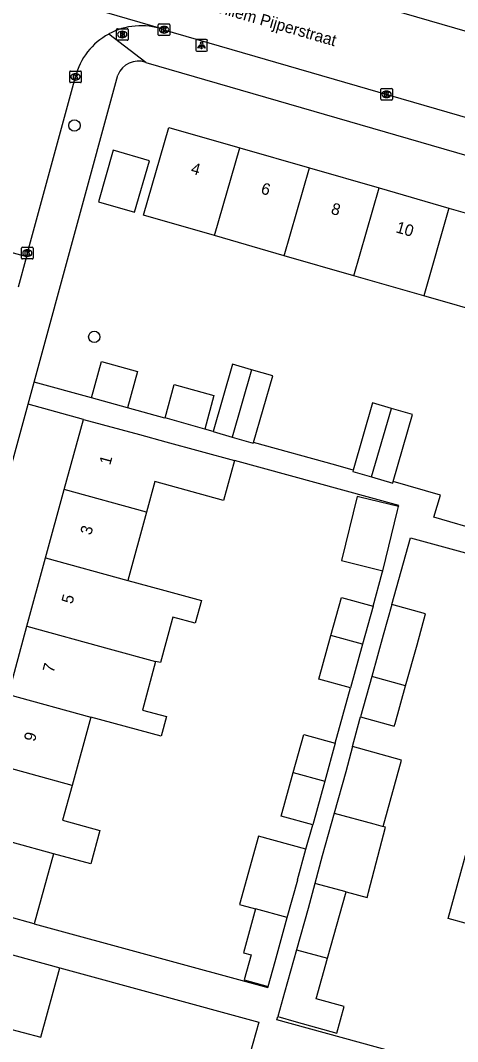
# Model space of a CAD drawing. Extents: x 159822 to 160765, y 380693 to 381634.
# Drawn here: x 160334.7 to 160372.4, y 381088.7 to 381176.6 of the extents above; entities that cross this region are included whole.
import ezdxf

# ---------------------------------------------------------------- set-up
doc = ezdxf.new("R2010")
doc.units = 0
for name, color, linetype in [('IMGEO_Boom', 7, 'Continuous'), ('IMGEO_Brandkraan', 7, 'Continuous'), ('IMGEO_Kolk', 7, 'Continuous'), ('IMGEO_Lichtpunt', 7, 'Continuous'), ('IMGEO_Openbare_ruimte_label', 7, 'Continuous'), ('IMGEO_Pand', 7, 'Continuous'), ('IMGEO_Pand_nummerreeks', 7, 'Continuous'), ('IMGEO_Rijbaan_lokaal_open', 7, 'Continuous'), ('IMGEO_Voetpad_open', 7, 'Continuous')]:
    doc.layers.add(name, color=color, linetype=linetype)

msp = doc.modelspace()

# ---------------------------------------------------------------- linework, layer by layer
at = {"layer": 'IMGEO_Boom'}
for centre in [(160339.349, 381167.541), (160341.058, 381149.34)]:
    msp.add_circle(centre, 0.489, dxfattribs=at)
at = {"layer": 'IMGEO_Brandkraan'}
for p, q in [((160342.97, 381174.95), (160342.97, 381175.802)), ((160343.045, 381175.876), (160343.897, 381175.876)), ((160343.458, 381175.656), (160343.483, 381175.656)), ((160343.971, 381175.802), (160343.971, 381174.95)), ((160343.897, 381174.876), (160343.045, 381174.876)), ((160343.481, 381175.096), (160343.456, 381175.096))]:
    msp.add_line(p, q, dxfattribs=at)
for points in [[(160342.97, 381174.95), (160342.97, 381175.802)], [(160343.045, 381175.876), (160343.897, 381175.876)], [(160343.318, 381175.576), (160343.318, 381175.176), (160343.531, 381175.176)], [(160343.549, 381175.576), (160343.318, 381175.576)], [(160343.497, 381175.495), (160343.443, 381175.495), (160343.443, 381175.419)], [(160343.443, 381175.419), (160343.496, 381175.419)], [(160343.971, 381175.802), (160343.971, 381174.95)], [(160343.897, 381174.876), (160343.045, 381174.876)], [(160343.505, 381175.343), (160343.443, 381175.343), (160343.443, 381175.262)], [(160343.443, 381175.262), (160343.505, 381175.262)]]:
    msp.add_lwpolyline(points, dxfattribs=at)
for centre, radius, start, end in [((160343.047, 381175.8), 0.0765, 91.55205, 178.44795), ((160343.047, 381175.8), 0.0765, 91.55205, 178.44795), ((160343.498, 381175.457), 0.0379, 267.82845, 90.93552), ((160343.553, 381175.431), 0.145, 59.4692, 91.53667), ((160343.578, 381175.478), 0.0922, 285.51372, 58.15012), ((160343.583, 381175.286), 0.105, 301.31148, 78.98903), ((160343.895, 381175.8), 0.0765, 1.55205, 88.44795), ((160343.895, 381175.8), 0.0765, 1.55205, 88.44795), ((160343.047, 381174.952), 0.0765, 181.55205, 268.44795), ((160343.047, 381174.952), 0.0765, 181.55205, 268.44795), ((160343.506, 381175.302), 0.0404, 269.87594, 90.50774), ((160343.537, 381175.427), 0.251, 268.66757, 293.53466), ((160343.895, 381174.952), 0.0765, 271.55205, 358.44795), ((160343.895, 381174.952), 0.0765, 271.55205, 358.44795)]:
    msp.add_arc(centre, radius, start, end, dxfattribs=at)
for centre, major_axis, ratio, start_param, end_param in [((160343.457, 381175.376), (-0.387, 0.002), 0.722429, 4.712389, 7.853982), ((160343.482, 381175.376), (-0.39, 0.002), 0.717154, 1.570796, 4.712389)]:
    msp.add_ellipse(centre, major_axis=major_axis, ratio=ratio, start_param=start_param, end_param=end_param, dxfattribs=at)
at = {"layer": 'IMGEO_Kolk'}
for p, q in [((160346.646, 381176.283), (160347.498, 381176.283)), ((160346.571, 381175.357), (160346.571, 381176.209)), ((160347.082, 381175.503), (160347.057, 381175.503)), ((160347.059, 381176.063), (160347.084, 381176.063)), ((160347.572, 381176.209), (160347.572, 381175.357)), ((160347.498, 381175.283), (160346.646, 381175.283)), ((160338.939, 381171.305), (160338.939, 381172.157)), ((160339.014, 381172.231), (160339.866, 381172.231)), ((160339.427, 381172.011), (160339.452, 381172.011)), ((160339.94, 381172.157), (160339.94, 381171.305)), ((160339.866, 381171.231), (160339.014, 381171.231)), ((160339.45, 381171.451), (160339.425, 381171.451)), ((160365.741, 381169.804), (160365.741, 381170.656)), ((160365.816, 381170.73), (160366.668, 381170.73)), ((160366.229, 381170.51), (160366.254, 381170.51)), ((160366.742, 381170.656), (160366.742, 381169.804)), ((160366.668, 381169.73), (160365.816, 381169.73)), ((160366.252, 381169.95), (160366.227, 381169.95)), ((160334.789, 381156.126), (160334.789, 381156.978)), ((160334.864, 381157.052), (160335.716, 381157.052)), ((160335.79, 381156.978), (160335.79, 381156.126)), ((160335.716, 381156.052), (160334.864, 381156.052)), ((160335.3, 381156.272), (160335.275, 381156.272)), ((160335.277, 381156.832), (160335.302, 381156.832))]:
    msp.add_line(p, q, dxfattribs=at)
for points in [[(160346.646, 381176.283), (160347.498, 381176.283)], [(160346.571, 381175.357), (160346.571, 381176.209)], [(160346.892, 381175.983), (160347.015, 381175.983), (160347.015, 381175.832), (160347.145, 381175.983), (160347.309, 381175.983), (160347.163, 381175.832), (160347.316, 381175.583), (160347.164, 381175.583), (160347.079, 381175.747), (160347.015, 381175.68), (160347.015, 381175.583), (160346.892, 381175.583), (160346.892, 381175.983)], [(160347.572, 381176.209), (160347.572, 381175.357)], [(160347.498, 381175.283), (160346.646, 381175.283)], [(160338.939, 381171.305), (160338.939, 381172.157)], [(160339.014, 381172.231), (160339.866, 381172.231)], [(160339.26, 381171.931), (160339.383, 381171.931), (160339.383, 381171.78), (160339.513, 381171.931), (160339.677, 381171.931), (160339.531, 381171.78), (160339.684, 381171.531), (160339.532, 381171.531), (160339.447, 381171.695), (160339.383, 381171.628), (160339.383, 381171.531), (160339.26, 381171.531), (160339.26, 381171.931)], [(160339.94, 381172.157), (160339.94, 381171.305)], [(160339.866, 381171.231), (160339.014, 381171.231)], [(160365.741, 381169.804), (160365.741, 381170.656)], [(160365.816, 381170.73), (160366.668, 381170.73)], [(160366.062, 381170.43), (160366.185, 381170.43), (160366.185, 381170.279), (160366.315, 381170.43), (160366.479, 381170.43), (160366.333, 381170.279), (160366.486, 381170.03), (160366.334, 381170.03), (160366.249, 381170.194), (160366.185, 381170.127), (160366.185, 381170.03), (160366.062, 381170.03), (160366.062, 381170.43)], [(160366.742, 381170.656), (160366.742, 381169.804)], [(160366.668, 381169.73), (160365.816, 381169.73)], [(160334.789, 381156.126), (160334.789, 381156.978)], [(160334.864, 381157.052), (160335.716, 381157.052)], [(160335.79, 381156.978), (160335.79, 381156.126)], [(160335.716, 381156.052), (160334.864, 381156.052)], [(160335.11, 381156.752), (160335.233, 381156.752), (160335.233, 381156.601), (160335.363, 381156.752), (160335.527, 381156.752), (160335.381, 381156.601), (160335.534, 381156.352), (160335.382, 381156.352), (160335.297, 381156.516), (160335.233, 381156.449), (160335.233, 381156.352), (160335.11, 381156.352), (160335.11, 381156.752)]]:
    msp.add_lwpolyline(points, dxfattribs=at)
for centre, start, end in [((160346.648, 381176.207), 91.55205, 178.44795), ((160346.648, 381176.207), 91.55205, 178.44795), ((160347.496, 381176.207), 1.55205, 88.44795), ((160347.496, 381176.207), 1.55205, 88.44795), ((160346.648, 381175.359), 181.55205, 268.44795), ((160346.648, 381175.359), 181.55205, 268.44795), ((160347.496, 381175.359), 271.55205, 358.44795), ((160347.496, 381175.359), 271.55205, 358.44795), ((160339.016, 381172.155), 91.55205, 178.44795), ((160339.016, 381172.155), 91.55205, 178.44795), ((160339.864, 381172.155), 1.55205, 88.44795), ((160339.864, 381172.155), 1.55205, 88.44795), ((160339.016, 381171.307), 181.55205, 268.44795), ((160339.016, 381171.307), 181.55205, 268.44795), ((160339.864, 381171.307), 271.55205, 358.44795), ((160339.864, 381171.307), 271.55205, 358.44795), ((160365.818, 381170.654), 91.55205, 178.44795), ((160365.818, 381170.654), 91.55205, 178.44795), ((160366.666, 381170.654), 1.55205, 88.44795), ((160366.666, 381170.654), 1.55205, 88.44795), ((160365.818, 381169.806), 181.55205, 268.44795), ((160365.818, 381169.806), 181.55205, 268.44795), ((160366.666, 381169.806), 271.55205, 358.44795), ((160366.666, 381169.806), 271.55205, 358.44795), ((160334.866, 381156.976), 91.55205, 178.44795), ((160334.866, 381156.976), 91.55205, 178.44795), ((160335.714, 381156.976), 1.55205, 88.44795), ((160335.714, 381156.976), 1.55205, 88.44795), ((160334.866, 381156.128), 181.55205, 268.44795), ((160334.866, 381156.128), 181.55205, 268.44795), ((160335.714, 381156.128), 271.55205, 358.44795), ((160335.714, 381156.128), 271.55205, 358.44795)]:
    msp.add_arc(centre, 0.0765, start, end, dxfattribs=at)
for centre, major_axis, ratio, start_param, end_param in [((160347.058, 381175.783), (-0.387, 0.002), 0.722429, 4.712389, 7.853982), ((160347.083, 381175.783), (-0.39, 0.002), 0.717154, 1.570796, 4.712389), ((160339.426, 381171.731), (-0.387, 0.002), 0.722429, 4.712389, 7.853982), ((160339.451, 381171.731), (-0.39, 0.002), 0.717154, 1.570796, 4.712389), ((160366.228, 381170.23), (-0.387, 0.002), 0.722429, 4.712389, 7.853982), ((160366.253, 381170.23), (-0.39, 0.002), 0.717154, 1.570796, 4.712389), ((160335.276, 381156.552), (-0.387, 0.002), 0.722429, 4.712389, 7.853982), ((160335.301, 381156.552), (-0.39, 0.002), 0.717154, 1.570796, 4.712389)]:
    msp.add_ellipse(centre, major_axis=major_axis, ratio=ratio, start_param=start_param, end_param=end_param, dxfattribs=at)
at = {"layer": 'IMGEO_Lichtpunt'}
for p, q in [((160349.802, 381174.836), (160349.802, 381174.029)), ((160349.802, 381174.836), (160349.802, 381174.029)), ((160350.704, 381174.931), (160349.896, 381174.931)), ((160350.704, 381174.931), (160349.896, 381174.931)), ((160350.798, 381174.029), (160350.798, 381174.836)), ((160350.798, 381174.029), (160350.798, 381174.836)), ((160349.896, 381173.935), (160350.704, 381173.935)), ((160349.896, 381173.935), (160350.704, 381173.935))]:
    msp.add_line(p, q, dxfattribs=at)
for points in [[(160350.176, 381174.5), (160350.215, 381174.472), (160350.027, 381174.21), (160349.989, 381174.237), (160350.176, 381174.5)], [(160350.278, 381174.452), (160350.325, 381174.452), (160350.325, 381174.13), (160350.278, 381174.13), (160350.278, 381174.452)], [(160350.388, 381174.472), (160350.426, 381174.499), (160350.613, 381174.237), (160350.574, 381174.209), (160350.388, 381174.472)]]:
    msp.add_lwpolyline(points, dxfattribs=at)
msp.add_circle((160350.301, 381174.634), 0.0994, dxfattribs=at)
for centre, start, end in [((160349.896, 381174.836), 90, 180), ((160349.896, 381174.836), 90, 180), ((160350.704, 381174.836), 0, 90), ((160350.704, 381174.836), 0, 90), ((160349.896, 381174.029), 180, 270), ((160349.896, 381174.029), 180, 270), ((160350.704, 381174.029), 270, 0), ((160350.704, 381174.029), 270, 360)]:
    msp.add_arc(centre, 0.0946, start, end, dxfattribs=at)
at = {"layer": 'IMGEO_Pand'}
for points in [[(160351.418, 381158.055), (160345.296, 381159.816), (160347.471, 381167.376), (160353.593, 381165.615)], [(160341.418, 381160.966), (160344.532, 381160.07), (160345.81, 381164.512), (160342.696, 381165.408), (160341.418, 381160.966)], [(160351.418, 381158.055), (160353.593, 381165.615)], [(160353.593, 381165.615), (160359.601, 381163.887)], [(160357.426, 381156.326), (160359.601, 381163.887)], [(160359.601, 381163.887), (160365.608, 381162.159)], [(160363.433, 381154.598), (160365.608, 381162.159)], [(160365.608, 381162.159), (160371.616, 381160.43)], [(160371.616, 381160.43), (160369.441, 381152.87)], [(160371.616, 381160.43), (160377.622, 381158.703)], [(160357.426, 381156.326), (160351.418, 381158.055)], [(160363.433, 381154.598), (160357.426, 381156.326)], [(160369.441, 381152.87), (160363.433, 381154.598)], [(160375.447, 381151.142), (160369.441, 381152.87)], [(160340.821, 381144.08), (160341.675, 381147.212), (160344.775, 381146.366), (160343.92, 381143.235)], [(160354.602, 381146.513), (160352.974, 381146.982), (160351.308, 381141.202)], [(160354.602, 381146.513), (160352.933, 381140.712)], [(160354.774, 381140.248), (160356.428, 381145.987), (160354.602, 381146.513)], [(160347.152, 381142.38), (160347.93, 381145.236), (160351.365, 381144.299), (160350.575, 381141.403)], [(160343.92, 381143.235), (160340.821, 381144.08)], [(160366.654, 381143.186), (160365.026, 381143.655), (160363.358, 381137.869)], [(160364.955, 381137.281), (160366.654, 381143.186)], [(160366.815, 381136.881), (160368.48, 381142.66), (160366.654, 381143.186)], [(160338.469, 381136.196), (160340.117, 381142.237)], [(160340.117, 381142.237), (160344.941, 381140.921), (160347.21, 381140.302), (160353.135, 381138.686)], [(160350.575, 381141.403), (160350.572, 381141.393), (160347.152, 381142.38)], [(160351.308, 381141.202), (160351.302, 381141.182), (160352.933, 381140.712)], [(160352.933, 381140.712), (160354.756, 381140.186), (160354.774, 381140.248)], [(160353.135, 381138.686), (160352.201, 381135.261), (160346.276, 381136.878), (160345.562, 381134.261)], [(160363.358, 381137.869), (160363.324, 381137.752), (160364.955, 381137.281)], [(160364.955, 381137.281), (160366.779, 381136.755), (160366.815, 381136.881)], [(160336.864, 381130.311), (160338.469, 381136.196)], [(160345.562, 381134.261), (160338.469, 381136.196)], [(160367.279, 381134.723), (160363.925, 381135.551), (160363.711, 381135.604), (160362.351, 381130.09), (160365.918, 381129.21)], [(160345.562, 381134.261), (160343.957, 381128.377)], [(160365.918, 381129.21), (160367.194, 381134.381), (160367.279, 381134.723)], [(160335.259, 381124.426), (160336.864, 381130.311)], [(160336.864, 381130.311), (160343.957, 381128.377)], [(160343.957, 381128.377), (160346.818, 381127.597), (160350.288, 381126.651), (160349.754, 381124.694), (160347.831, 381125.218), (160347.772, 381125.002), (160346.76, 381121.29), (160346.344, 381121.403)], [(160361.448, 381123.64), (160362.351, 381126.897), (160365.076, 381126.141)], [(160366.699, 381126.297), (160365.959, 381123.644), (160364.971, 381120.1)], [(160367.88, 381119.305), (160368.864, 381122.834), (160369.604, 381125.487), (160366.699, 381126.297)], [(160365.076, 381126.141), (160364.177, 381122.896)], [(160333.654, 381118.54), (160335.259, 381124.426)], [(160335.259, 381124.426), (160342.352, 381122.491), (160346.344, 381121.403)], [(160363.13, 381119.119), (160360.404, 381119.874), (160361.448, 381123.64)], [(160364.177, 381122.896), (160361.448, 381123.64)], [(160364.177, 381122.896), (160363.13, 381119.119)], [(160346.344, 381121.403), (160345.2, 381117.21), (160347.269, 381116.646), (160346.807, 381114.953), (160340.747, 381116.605)], [(160364.971, 381120.1), (160364, 381116.618)], [(160367.88, 381119.305), (160364.971, 381120.1)], [(160364, 381116.618), (160366.905, 381115.808), (160366.974, 381116.052), (160367.88, 381119.305)], [(160333.654, 381118.54), (160340.747, 381116.605)], [(160340.747, 381116.605), (160339.142, 381110.721)], [(160358.198, 381111.844), (160359.1, 381115.101), (160361.826, 381114.345)], [(160361.826, 381114.345), (160360.926, 381111.1)], [(160363.312, 381114.081), (160362.718, 381111.883), (160361.73, 381108.339)], [(160365.94, 381107.189), (160367.533, 381112.903), (160363.312, 381114.081)], [(160339.142, 381110.721), (160332.049, 381112.655)], [(160359.879, 381107.323), (160357.154, 381108.078), (160358.198, 381111.844)], [(160358.198, 381111.844), (160360.926, 381111.1)], [(160339.142, 381110.721), (160338.323, 381107.719), (160341.543, 381106.841), (160340.756, 381103.958), (160337.537, 381104.836)], [(160360.926, 381111.1), (160359.879, 381107.323)], [(160361.73, 381108.339), (160360.702, 381104.651), (160360.062, 381102.288)], [(160361.73, 381108.339), (160365.138, 381107.408), (160365.94, 381107.189)], [(160362.747, 381101.556), (160364.557, 381101.061), (160364.613, 381101.273), (160364.681, 381101.536), (160366.15, 381107.131), (160365.94, 381107.189)], [(160337.537, 381104.836), (160330.444, 381106.77)], [(160359.298, 381105.224), (160355.213, 381106.338), (160353.582, 381100.459), (160353.763, 381100.409), (160354.956, 381100.084)], [(160357.685, 381099.34), (160358.585, 381102.585), (160358.568, 381102.59), (160359.298, 381105.224)], [(160377.083, 381097.776), (160374.484, 381098.449), (160371.548, 381099.251), (160373.176, 381105.211), (160376.112, 381104.409), (160379.525, 381103.477)], [(160337.537, 381104.836), (160335.891, 381098.801)], [(160360.062, 381102.288), (160359.475, 381100.121), (160358.487, 381096.577)], [(160362.747, 381101.556), (160360.062, 381102.288)], [(160361.155, 381095.848), (160362.747, 381101.556)], [(160335.891, 381098.801), (160333.622, 381099.42), (160328.798, 381100.736)], [(160354.956, 381100.084), (160353.912, 381096.318), (160354.58, 381096.133), (160353.984, 381093.982), (160356.042, 381093.411)], [(160357.685, 381099.34), (160354.956, 381100.084)], [(160356.042, 381093.411), (160356.638, 381095.562), (160357.685, 381099.34)], [(160328.006, 381097.753), (160332.83, 381096.438), (160338.079, 381095.007)], [(160358.487, 381096.577), (160357.459, 381092.889), (160356.88, 381090.813)], [(160358.487, 381096.577), (160361.155, 381095.848)], [(160356.88, 381090.813), (160358.446, 381090.376), (160361.942, 381089.402), (160362.578, 381091.683), (160360.181, 381092.351), (160361.155, 381095.848)], [(160333.407, 381089.86), (160336.452, 381089.045), (160338.079, 381095.007)]]:
    msp.add_lwpolyline(points, dxfattribs=at)
at = {"layer": 'IMGEO_Rijbaan_lokaal_open'}
for points in [[(160346.957, 381175.818), (160346.8, 381175.9), (160329.938, 381180.803), (160329.797, 381180.826)], [(160375.389, 381174.985), (160358.816, 381179.79)], [(160346.957, 381175.818), (160373.409, 381168.155)], [(160335.211, 381156.266), (160339.431, 381171.726)], [(160329.797, 381157.745), (160335.211, 381156.266)], [(160335.211, 381156.266), (160334.487, 381153.613)]]:
    msp.add_lwpolyline(points, dxfattribs=at)
for centre, radius, start, end in [((160345.085, 381170.294), 5.833, 118.53426, 165.78457), ((160345.085, 381170.293), 5.834, 71.28639, 118.52994)]:
    msp.add_arc(centre, radius, start, end, dxfattribs=at)
at = {"layer": 'IMGEO_Voetpad_open'}
for points in [[(160345.496, 381172.978), (160342.299, 381175.418)], [(160345.496, 381172.978), (160407.146, 381155.127)], [(160335.866, 381145.432), (160343.078, 381171.876)], [(160335.349, 381143.537), (160335.866, 381145.432)], [(160340.821, 381144.08), (160335.866, 381145.432)], [(160324.03, 381102.036), (160335.349, 381143.537)], [(160340.117, 381142.237), (160335.349, 381143.537)], [(160347.152, 381142.38), (160347.143, 381142.348), (160343.92, 381143.235)], [(160351.308, 381141.202), (160350.575, 381141.403)], [(160363.358, 381137.869), (160361.864, 381138.296), (160354.774, 381140.248)], [(160367.279, 381134.723), (160367.303, 381134.822), (160353.135, 381138.686)], [(160374.662, 381132.566), (160370.326, 381133.806), (160370.874, 381135.721), (160366.815, 381136.881)], [(160366.699, 381126.297), (160368.301, 381132.044), (160388.392, 381126.555)], [(160365.076, 381126.141), (160365.873, 381129.027), (160365.918, 381129.21)], [(160361.826, 381114.345), (160363.13, 381119.119)], [(160363.312, 381114.081), (160363.943, 381116.412), (160364, 381116.618)], [(160359.298, 381105.224), (160359.879, 381107.323)], [(160335.891, 381098.801), (160356.014, 381093.311), (160356.042, 381093.411)], [(160338.079, 381095.007), (160355.224, 381090.333), (160354.458, 381087.57)], [(160376.964, 381085.008), (160356.8, 381090.525), (160356.88, 381090.813)]]:
    msp.add_lwpolyline(points, dxfattribs=at)
msp.add_arc((160344.868, 381171.152), 1.931, 71.01887, 157.98324, dxfattribs=at)

# ---------------------------------------------------------------- texts
at = {"layer": 'IMGEO_Openbare_ruimte_label'}
msp.add_text('Willem Pijperstraat', height=1, rotation=343.92083, dxfattribs=at).set_placement((160351.033, 381177.444))
at = {"layer": 'IMGEO_Pand_nummerreeks'}
for s, rotation, p in [('4', 343.95153, (160349.316, 381163.431)), ('6', 343.95153, (160355.349, 381161.696)), ('8', 343.95153, (160361.387, 381159.959)), ('10', 343.95153, (160366.977, 381158.352)), ('1', 74.74418, (160342.43, 381138.255)), ('3', 74.74234, (160340.784, 381132.216)), ('5', 74.74234, (160339.167, 381126.287)), ('7', 74.74418, (160337.549, 381120.358)), ('9', 74.74418, (160335.932, 381114.43))]:
    msp.add_text(s, height=1, rotation=rotation, dxfattribs=at).set_placement(p)

doc.saveas('drawing.dxf')
